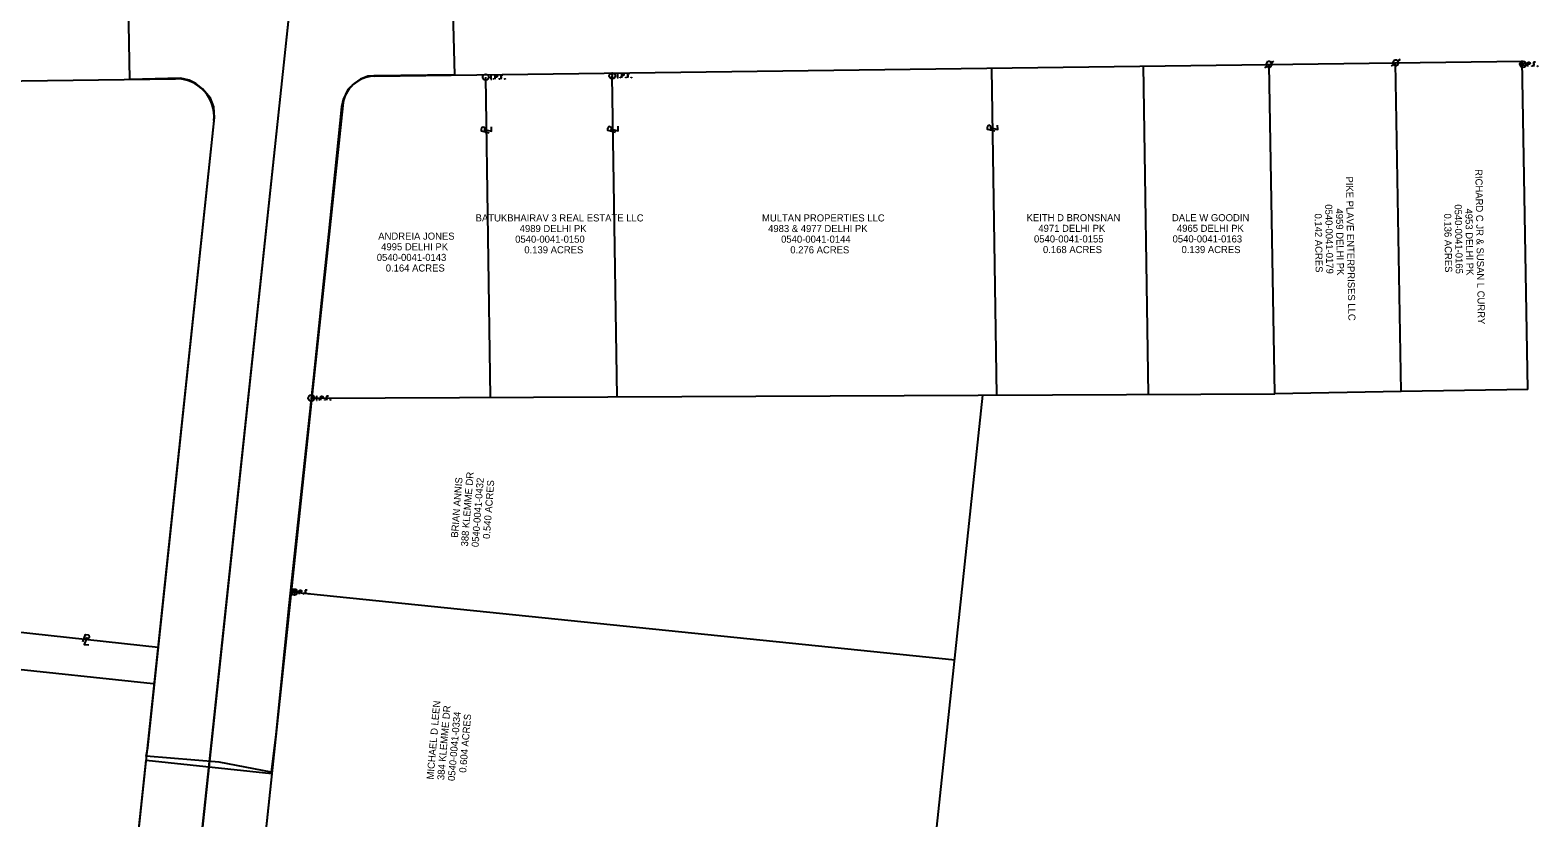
# Model space of a CAD drawing. Extents: x 1369159 to 1370720, y 404461 to 406422.
# Drawn here: x 1369920 to 1370515, y 405578 to 405889 of the extents above; entities that cross this region are included whole.
import ezdxf

# ---------------------------------------------------------------- set-up
doc = ezdxf.new("R2010")
doc.units = 0
for name, color, linetype in [('_CIVIL_CONSTRUCTION', 7, 'Continuous'), ('Default', 7, 'Continuous'), ('DR_P_Cells', 7, 'Continuous'), ('DR_P_Storm_Sewer', 7, 'Continuous'), ('DR_X_Cells', 7, 'Continuous'), ('GK_Drainage_Nodes', 7, 'Continuous'), ('PF_X_Ground_Line', 7, 'Continuous'), ('SC_Scratch1', 7, 'Continuous'), ('UT_X_Water', 7, 'Continuous'), ('XS_X_Pavt', 7, 'Continuous'), ('XS_X_Subgrade', 7, 'Continuous')]:
    doc.layers.add(name, color=color, linetype=linetype)

msp = doc.modelspace()

# ---------------------------------------------------------------- linework, layer by layer
at = {"layer": '_CIVIL_CONSTRUCTION'}
for p, q in [((1370408.45, 405875), (1370407.49, 405874.28)), ((1370408.1, 405875.6), (1370408.81, 405876.8)), ((1370408.81, 405874.39), (1370408.1, 405875.6)), ((1370408.81, 405876.8), (1370409.71, 405876.8)), ((1370409.71, 405874.39), (1370408.81, 405874.39)), ((1370409.71, 405876.8), (1370410.42, 405875.6)), ((1370410.42, 405875.6), (1370409.71, 405874.39)), ((1370411.03, 405876.92), (1370410.07, 405876.2)), ((1370458.44, 405875.63), (1370457.47, 405874.91)), ((1370458.08, 405876.23), (1370458.79, 405877.43)), ((1370458.79, 405875.03), (1370458.08, 405876.23)), ((1370458.79, 405877.43), (1370459.69, 405877.43)), ((1370459.69, 405875.03), (1370458.79, 405875.03)), ((1370459.69, 405877.43), (1370460.4, 405876.23)), ((1370460.4, 405876.23), (1370459.69, 405875.03)), ((1370461.01, 405877.55), (1370460.05, 405876.83))]:
    msp.add_line(p, q, dxfattribs=at)
at = {"layer": 'Default'}
for p, q in [((1370411.48, 405745.39), (1370409.21, 405875.37)), ((1370461.47, 405746.26), (1370459.2, 405876.24)), ((1370511.46, 405747.13), (1370509.2, 405877.11)), ((1370511.46, 405747.13), (1370461.47, 405746.26)), ((1370461.47, 405746.26), (1370411.48, 405745.39))]:
    msp.add_line(p, q, dxfattribs=at)
at = {"layer": 'DR_P_Cells'}
msp.add_line((1370077.92, 406421.94), (1369968.9, 405398.85), dxfattribs=at)
at = {"layer": 'DR_P_Storm_Sewer'}
for p, q in [((1370301.59, 405744.9), (1370299.61, 405873.78)), ((1370361.6, 405745.17), (1370359.6, 405875.04)), ((1370101.6, 405744.01), (1370099.65, 405870.55)), ((1370151.59, 405744.23), (1370149.64, 405871.08)), ((1370099.36, 405848.84), (1370099.34, 405850.14)), ((1370099.97, 405849.66), (1370099.97, 405849.66)), ((1370149.35, 405849.07), (1370149.33, 405850.36)), ((1370149.96, 405849.88), (1370149.96, 405849.88)), ((1370299.36, 405849.54), (1370299.34, 405850.83)), ((1370299.97, 405850.35), (1370299.97, 405850.35)), ((1370030.71, 405743.69), (1370411.48, 405745.39)), ((1370274.45, 405540.93), (1370296.13, 405744.87)), ((1369970.15, 405645.1), (1369714.82, 405673.24)), ((1370024.06, 405667.03), (1370285.18, 405640.18)), ((1369941.02, 405648.94), (1369942.31, 405648.8)), ((1369941.75, 405648.23), (1369941.75, 405648.23))]:
    msp.add_line(p, q, dxfattribs=at)
for points in [[(1370100.96, 405848.45), (1370097.98, 405849.18), (1370097.97, 405850.22)], [(1370099.01, 405849.91), (1370101.98, 405849.16), (1370101.95, 405850.91)], [(1370150.95, 405848.67), (1370147.97, 405849.41), (1370147.96, 405850.44)], [(1370149, 405850.13), (1370151.97, 405849.39), (1370151.94, 405851.13)], [(1370300.96, 405849.14), (1370297.98, 405849.88), (1370297.97, 405850.91)], [(1370299.01, 405850.6), (1370301.98, 405849.85), (1370301.95, 405851.6)], [(1369940.43, 405647.4), (1369941.53, 405650.26), (1369942.56, 405650.15)], [(1369942.12, 405649.15), (1369941.01, 405646.3), (1369942.75, 405646.11)]]:
    msp.add_lwpolyline(points, dxfattribs=at)
for centre, start, end in [((1370098.65, 405850.12), 1.35172, 172.20884), ((1370148.64, 405850.35), 1.35172, 172.20884), ((1370298.65, 405850.82), 1.35172, 172.20884), ((1369942.38, 405649.48), 264.18315, 75.04027)]:
    msp.add_arc(centre, 0.69, start, end, dxfattribs=at)
at = {"layer": 'DR_X_Cells'}
msp.add_lwpolyline([(1370085.17, 405950.93), (1370087.31, 405871.45), (1370055.38, 405871.07), (1370053, 405870.91), (1370050.13, 405869.76), (1370047.85, 405868.19), (1370045.21, 405865.67), (1370043.32, 405861.75), (1370042.61, 405858.87), (1370037.52, 405808.49), (1370035.46, 405788.7), (1370031.53, 405751.98), (1370021.79, 405661.72), (1370016.71, 405610.7), (1370014.88, 405595.8), (1369994.27, 405599.82), (1369965.52, 405602.15), (1369966.06, 405605.47), (1369992.47, 405854.56), (1369992.17, 405858.8), (1369990.88, 405862.22), (1369987.67, 405865.95), (1369985.12, 405868.06), (1369982.45, 405869.36), (1369979.09, 405870.17), (1369959, 405869.67), (1369957.54, 405949.66)], dxfattribs=at)
at = {"layer": 'PF_X_Ground_Line'}
msp.add_line((1369710.16, 405658.01), (1369968.29, 405630.88), dxfattribs=at)
at = {"layer": 'SC_Scratch1'}
for p, q in [((1370151.67, 405871.88), (1370152.02, 405871.88)), ((1370151.84, 405870.28), (1370151.84, 405871.88)), ((1370153.41, 405870.28), (1370153.41, 405871.88)), ((1370153.41, 405871.88), (1370153.94, 405871.88)), ((1370153.94, 405871.88), (1370153.99, 405871.87)), ((1370153.99, 405871.87), (1370154.07, 405871.84)), ((1370154.07, 405871.84), (1370154.1, 405871.82)), ((1370154.1, 405871.82), (1370154.14, 405871.79)), ((1370154.14, 405871.79), (1370154.18, 405871.73)), ((1370154.18, 405871.73), (1370154.21, 405871.67)), ((1370156.42, 405871.88), (1370155.66, 405871.88)), ((1370155.66, 405871.88), (1370155.66, 405870.28)), ((1370511.54, 405874.82), (1370511.54, 405876.42)), ((1370511.54, 405876.42), (1370512.07, 405876.42)), ((1370512.07, 405875.64), (1370511.54, 405875.64)), ((1370512.07, 405876.42), (1370512.13, 405876.41)), ((1370512.16, 405875.65), (1370512.07, 405875.64)), ((1370512.13, 405876.41), (1370512.2, 405876.38)), ((1370512.22, 405875.68), (1370512.16, 405875.65)), ((1370512.2, 405876.38), (1370512.24, 405876.36)), ((1370512.25, 405875.7), (1370512.22, 405875.68)), ((1370512.24, 405876.36), (1370512.27, 405876.33)), ((1370512.29, 405875.74), (1370512.25, 405875.7)), ((1370512.27, 405876.33), (1370512.31, 405876.27)), ((1370512.34, 405875.83), (1370512.29, 405875.74)), ((1370512.31, 405876.27), (1370512.35, 405876.2)), ((1370512.36, 405875.9), (1370512.34, 405875.83)), ((1370512.35, 405876.2), (1370512.37, 405876.1)), ((1370512.37, 405875.95), (1370512.36, 405875.9)), ((1370512.37, 405876.1), (1370512.37, 405875.95)), ((1370513.12, 405874.96), (1370513.15, 405875.01)), ((1370513.12, 405874.89), (1370513.12, 405874.96)), ((1370513.15, 405874.84), (1370513.12, 405874.89)), ((1370513.15, 405875.01), (1370513.19, 405875.03)), ((1370513.19, 405874.82), (1370513.15, 405874.84)), ((1370513.19, 405875.03), (1370513.24, 405875.03)), ((1370513.24, 405874.82), (1370513.19, 405874.82)), ((1370513.24, 405875.03), (1370513.27, 405875.01)), ((1370513.27, 405874.84), (1370513.24, 405874.82)), ((1370513.27, 405875.01), (1370513.31, 405874.96)), ((1370513.31, 405874.89), (1370513.27, 405874.84)), ((1370513.31, 405874.96), (1370513.31, 405874.89)), ((1370514.55, 405876.42), (1370513.79, 405876.42)), ((1370513.79, 405876.42), (1370513.79, 405874.82)), ((1370513.79, 405875.64), (1370514.33, 405875.64)), ((1370515.27, 405874.96), (1370515.3, 405875.01)), ((1370515.27, 405874.89), (1370515.27, 405874.96)), ((1370515.3, 405874.84), (1370515.27, 405874.89)), ((1370515.3, 405875.01), (1370515.34, 405875.03)), ((1370515.34, 405874.82), (1370515.3, 405874.84)), ((1370515.34, 405875.03), (1370515.39, 405875.03)), ((1370515.39, 405874.82), (1370515.34, 405874.82)), ((1370515.39, 405875.03), (1370515.42, 405875.01)), ((1370515.42, 405874.84), (1370515.39, 405874.82)), ((1370515.42, 405875.01), (1370515.46, 405874.96)), ((1370515.46, 405874.89), (1370515.42, 405874.84)), ((1370515.46, 405874.96), (1370515.46, 405874.89)), ((1370101.67, 405871.35), (1370102.02, 405871.35)), ((1370101.67, 405869.76), (1370102.02, 405869.76)), ((1370101.84, 405869.76), (1370101.84, 405871.35)), ((1370102.74, 405869.89), (1370102.77, 405869.94)), ((1370102.74, 405869.83), (1370102.74, 405869.89)), ((1370102.77, 405869.78), (1370102.74, 405869.83)), ((1370102.77, 405869.94), (1370102.8, 405869.97)), ((1370102.8, 405869.76), (1370102.77, 405869.78)), ((1370102.8, 405869.97), (1370102.86, 405869.97)), ((1370102.86, 405869.76), (1370102.8, 405869.76)), ((1370102.86, 405869.97), (1370102.89, 405869.94)), ((1370102.89, 405869.78), (1370102.86, 405869.76)), ((1370102.89, 405869.94), (1370102.92, 405869.89)), ((1370102.92, 405869.83), (1370102.89, 405869.78)), ((1370102.92, 405869.89), (1370102.92, 405869.83)), ((1370103.41, 405869.76), (1370103.41, 405871.35)), ((1370103.41, 405871.35), (1370103.94, 405871.35)), ((1370103.94, 405870.57), (1370103.41, 405870.57)), ((1370103.94, 405871.35), (1370103.99, 405871.34)), ((1370104.03, 405870.59), (1370103.94, 405870.57)), ((1370103.99, 405871.34), (1370104.07, 405871.32)), ((1370104.08, 405870.61), (1370104.03, 405870.59)), ((1370104.07, 405871.32), (1370104.1, 405871.29)), ((1370104.11, 405870.64), (1370104.08, 405870.61)), ((1370104.1, 405871.29), (1370104.14, 405871.27)), ((1370104.16, 405870.67), (1370104.11, 405870.64)), ((1370104.14, 405871.27), (1370104.18, 405871.2)), ((1370104.2, 405870.76), (1370104.16, 405870.67)), ((1370104.18, 405871.2), (1370104.21, 405871.14)), ((1370104.22, 405870.84), (1370104.2, 405870.76)), ((1370104.21, 405871.14), (1370104.24, 405871.04)), ((1370104.24, 405870.89), (1370104.22, 405870.84)), ((1370104.24, 405871.04), (1370104.24, 405870.89)), ((1370104.99, 405869.89), (1370105.02, 405869.94)), ((1370104.99, 405869.83), (1370104.99, 405869.89)), ((1370105.02, 405869.78), (1370104.99, 405869.83)), ((1370105.02, 405869.94), (1370105.05, 405869.97)), ((1370105.05, 405869.76), (1370105.02, 405869.78)), ((1370105.05, 405869.97), (1370105.11, 405869.97)), ((1370105.11, 405869.76), (1370105.05, 405869.76)), ((1370105.11, 405869.97), (1370105.14, 405869.94)), ((1370105.14, 405869.78), (1370105.11, 405869.76)), ((1370105.14, 405869.94), (1370105.17, 405869.89)), ((1370105.17, 405869.83), (1370105.14, 405869.78)), ((1370105.17, 405869.89), (1370105.17, 405869.83)), ((1370106.42, 405871.35), (1370105.66, 405871.35)), ((1370105.66, 405871.35), (1370105.66, 405869.76)), ((1370105.66, 405870.57), (1370106.2, 405870.57)), ((1370107.13, 405869.89), (1370107.17, 405869.94)), ((1370107.13, 405869.83), (1370107.13, 405869.89)), ((1370107.17, 405869.78), (1370107.13, 405869.83)), ((1370107.17, 405869.94), (1370107.2, 405869.97)), ((1370107.2, 405869.76), (1370107.17, 405869.78)), ((1370107.2, 405869.97), (1370107.26, 405869.97)), ((1370107.26, 405869.76), (1370107.2, 405869.76)), ((1370107.26, 405869.97), (1370107.29, 405869.94)), ((1370107.29, 405869.78), (1370107.26, 405869.76)), ((1370107.29, 405869.94), (1370107.32, 405869.89)), ((1370107.32, 405869.83), (1370107.29, 405869.78)), ((1370107.32, 405869.89), (1370107.32, 405869.83)), ((1370149.64, 405871.2), (1370149.64, 405870.31)), ((1370151.67, 405870.28), (1370152.02, 405870.28)), ((1370152.74, 405870.42), (1370152.77, 405870.47)), ((1370152.74, 405870.36), (1370152.74, 405870.42)), ((1370152.77, 405870.31), (1370152.74, 405870.36)), ((1370152.77, 405870.47), (1370152.8, 405870.49)), ((1370152.8, 405870.28), (1370152.77, 405870.31)), ((1370152.8, 405870.49), (1370152.86, 405870.49)), ((1370152.86, 405870.28), (1370152.8, 405870.28)), ((1370152.86, 405870.49), (1370152.89, 405870.47)), ((1370152.89, 405870.31), (1370152.86, 405870.28)), ((1370152.89, 405870.47), (1370152.92, 405870.42)), ((1370152.92, 405870.36), (1370152.89, 405870.31)), ((1370152.92, 405870.42), (1370152.92, 405870.36)), ((1370153.94, 405871.1), (1370153.41, 405871.1)), ((1370154.03, 405871.11), (1370153.94, 405871.1)), ((1370154.08, 405871.14), (1370154.03, 405871.11)), ((1370154.12, 405871.16), (1370154.08, 405871.14)), ((1370154.16, 405871.2), (1370154.12, 405871.16)), ((1370154.2, 405871.29), (1370154.16, 405871.2)), ((1370154.23, 405871.36), (1370154.2, 405871.29)), ((1370154.21, 405871.67), (1370154.24, 405871.56)), ((1370154.24, 405871.41), (1370154.23, 405871.36)), ((1370154.24, 405871.56), (1370154.24, 405871.41)), ((1370154.99, 405870.42), (1370155.02, 405870.47)), ((1370154.99, 405870.36), (1370154.99, 405870.42)), ((1370155.02, 405870.31), (1370154.99, 405870.36)), ((1370155.02, 405870.47), (1370155.05, 405870.49)), ((1370155.05, 405870.28), (1370155.02, 405870.31)), ((1370155.05, 405870.49), (1370155.11, 405870.49)), ((1370155.11, 405870.28), (1370155.05, 405870.28)), ((1370155.11, 405870.49), (1370155.14, 405870.47)), ((1370155.14, 405870.31), (1370155.11, 405870.28)), ((1370155.14, 405870.47), (1370155.17, 405870.42)), ((1370155.17, 405870.36), (1370155.14, 405870.31)), ((1370155.17, 405870.42), (1370155.17, 405870.36)), ((1370155.66, 405871.1), (1370156.2, 405871.1)), ((1370157.14, 405870.42), (1370157.17, 405870.47)), ((1370157.14, 405870.36), (1370157.14, 405870.42)), ((1370157.17, 405870.31), (1370157.14, 405870.36)), ((1370157.17, 405870.47), (1370157.2, 405870.49)), ((1370157.2, 405870.28), (1370157.17, 405870.31)), ((1370157.2, 405870.49), (1370157.26, 405870.49)), ((1370157.26, 405870.28), (1370157.2, 405870.28)), ((1370157.26, 405870.49), (1370157.29, 405870.47)), ((1370157.29, 405870.31), (1370157.26, 405870.28)), ((1370157.29, 405870.47), (1370157.32, 405870.42)), ((1370157.32, 405870.36), (1370157.29, 405870.31)), ((1370157.32, 405870.42), (1370157.32, 405870.36)), ((1370032.72, 405744.49), (1370033.07, 405744.49)), ((1370032.72, 405742.89), (1370033.07, 405742.89)), ((1370032.9, 405742.89), (1370032.9, 405744.49)), ((1370033.79, 405743.03), (1370033.82, 405743.08)), ((1370033.79, 405742.97), (1370033.79, 405743.03)), ((1370033.82, 405742.92), (1370033.79, 405742.97)), ((1370033.82, 405743.08), (1370033.86, 405743.11)), ((1370033.86, 405742.89), (1370033.82, 405742.92)), ((1370033.86, 405743.11), (1370033.91, 405743.11)), ((1370033.91, 405742.89), (1370033.86, 405742.89)), ((1370033.91, 405743.11), (1370033.95, 405743.08)), ((1370033.95, 405742.92), (1370033.91, 405742.89)), ((1370033.95, 405743.08), (1370033.98, 405743.03)), ((1370033.98, 405742.97), (1370033.95, 405742.92)), ((1370033.98, 405743.03), (1370033.98, 405742.97)), ((1370034.46, 405742.89), (1370034.46, 405744.49)), ((1370034.46, 405744.49), (1370034.99, 405744.49)), ((1370034.99, 405743.71), (1370034.46, 405743.71)), ((1370034.99, 405744.49), (1370035.05, 405744.48)), ((1370035.08, 405743.73), (1370034.99, 405743.71)), ((1370035.05, 405744.48), (1370035.12, 405744.46)), ((1370035.14, 405743.75), (1370035.08, 405743.73)), ((1370035.12, 405744.46), (1370035.16, 405744.43)), ((1370035.17, 405743.78), (1370035.14, 405743.75)), ((1370035.16, 405744.43), (1370035.19, 405744.41)), ((1370035.21, 405743.81), (1370035.17, 405743.78)), ((1370035.19, 405744.41), (1370035.23, 405744.34)), ((1370035.26, 405743.9), (1370035.21, 405743.81)), ((1370035.23, 405744.34), (1370035.27, 405744.28)), ((1370035.28, 405743.98), (1370035.26, 405743.9)), ((1370035.27, 405744.28), (1370035.29, 405744.18)), ((1370035.29, 405744.03), (1370035.28, 405743.98)), ((1370035.29, 405744.18), (1370035.29, 405744.03)), ((1370036.04, 405743.03), (1370036.07, 405743.08)), ((1370036.04, 405742.97), (1370036.04, 405743.03)), ((1370036.07, 405742.92), (1370036.04, 405742.97)), ((1370036.07, 405743.08), (1370036.11, 405743.11)), ((1370036.11, 405742.89), (1370036.07, 405742.92)), ((1370036.11, 405743.11), (1370036.16, 405743.11)), ((1370036.16, 405742.89), (1370036.11, 405742.89)), ((1370036.16, 405743.11), (1370036.19, 405743.08)), ((1370036.19, 405742.92), (1370036.16, 405742.89)), ((1370036.19, 405743.08), (1370036.23, 405743.03)), ((1370036.23, 405742.97), (1370036.19, 405742.92)), ((1370036.23, 405743.03), (1370036.23, 405742.97)), ((1370037.47, 405744.49), (1370036.71, 405744.49)), ((1370036.71, 405744.49), (1370036.71, 405742.89)), ((1370036.71, 405743.71), (1370037.25, 405743.71)), ((1370038.19, 405743.03), (1370038.22, 405743.08)), ((1370038.19, 405742.97), (1370038.19, 405743.03)), ((1370038.22, 405742.92), (1370038.19, 405742.97)), ((1370038.22, 405743.08), (1370038.25, 405743.11)), ((1370038.25, 405742.89), (1370038.22, 405742.92)), ((1370038.25, 405743.11), (1370038.31, 405743.11)), ((1370038.31, 405742.89), (1370038.25, 405742.89)), ((1370038.31, 405743.11), (1370038.34, 405743.08)), ((1370038.34, 405742.92), (1370038.31, 405742.89)), ((1370038.34, 405743.08), (1370038.38, 405743.03)), ((1370038.38, 405742.97), (1370038.34, 405742.92)), ((1370038.38, 405743.03), (1370038.38, 405742.97)), ((1370026.05, 405666.23), (1370026.05, 405667.83)), ((1370026.05, 405667.83), (1370026.58, 405667.83)), ((1370026.58, 405667.05), (1370026.05, 405667.05)), ((1370026.58, 405667.83), (1370026.64, 405667.82)), ((1370026.67, 405667.06), (1370026.58, 405667.05)), ((1370026.64, 405667.82), (1370026.71, 405667.79)), ((1370026.73, 405667.09), (1370026.67, 405667.06)), ((1370026.71, 405667.79), (1370026.75, 405667.77)), ((1370026.76, 405667.11), (1370026.73, 405667.09)), ((1370026.75, 405667.77), (1370026.78, 405667.74)), ((1370026.8, 405667.15), (1370026.76, 405667.11)), ((1370026.78, 405667.74), (1370026.82, 405667.68)), ((1370026.85, 405667.24), (1370026.8, 405667.15)), ((1370026.82, 405667.68), (1370026.86, 405667.62)), ((1370026.87, 405667.31), (1370026.85, 405667.24)), ((1370026.86, 405667.62), (1370026.88, 405667.51)), ((1370026.88, 405667.36), (1370026.87, 405667.31)), ((1370026.88, 405667.51), (1370026.88, 405667.36)), ((1370027.63, 405666.37), (1370027.66, 405666.42)), ((1370027.63, 405666.31), (1370027.63, 405666.37)), ((1370027.66, 405666.26), (1370027.63, 405666.31)), ((1370027.66, 405666.42), (1370027.7, 405666.44)), ((1370027.7, 405666.23), (1370027.66, 405666.26)), ((1370027.7, 405666.44), (1370027.75, 405666.44)), ((1370027.75, 405666.23), (1370027.7, 405666.23)), ((1370027.75, 405666.44), (1370027.78, 405666.42)), ((1370027.78, 405666.26), (1370027.75, 405666.23)), ((1370027.78, 405666.42), (1370027.82, 405666.37)), ((1370027.82, 405666.31), (1370027.78, 405666.26)), ((1370027.82, 405666.37), (1370027.82, 405666.31)), ((1370029.06, 405667.83), (1370028.3, 405667.83)), ((1370028.3, 405667.83), (1370028.3, 405666.23)), ((1370028.3, 405667.05), (1370028.84, 405667.05)), ((1370029.78, 405666.37), (1370029.81, 405666.42)), ((1370029.78, 405666.31), (1370029.78, 405666.37)), ((1370029.81, 405666.26), (1370029.78, 405666.31)), ((1370029.81, 405666.42), (1370029.85, 405666.44)), ((1370029.85, 405666.23), (1370029.81, 405666.26)), ((1370029.85, 405666.44), (1370029.9, 405666.44)), ((1370029.9, 405666.23), (1370029.85, 405666.23)), ((1370029.9, 405666.44), (1370029.93, 405666.42)), ((1370029.93, 405666.26), (1370029.9, 405666.23)), ((1370029.93, 405666.42), (1370029.97, 405666.37)), ((1370029.97, 405666.31), (1370029.93, 405666.26)), ((1370029.97, 405666.37), (1370029.97, 405666.31))]:
    msp.add_line(p, q, dxfattribs=at)
for centre, radius in [((1370099.65, 405870.55), 1.2), ((1370149.64, 405871.08), 1.2), ((1370149.64, 405871.73), 0.16), ((1370509.55, 405875.62), 1.2), ((1370509.55, 405875.62), 0.495), ((1370030.71, 405743.69), 1.2), ((1370024.06, 405667.03), 1.2), ((1370024.06, 405667.03), 0.495)]:
    msp.add_circle(centre, radius, dxfattribs=at)
at = {"layer": 'UT_X_Water'}
msp.add_lwpolyline([(1369941.6, 405376.85), (1369965.4, 405600.58), (1370015.12, 405595.3), (1369991.32, 405371.56), (1369966.44, 405374.21)], dxfattribs=at)
at = {"layer": 'XS_X_Pavt'}
msp.add_line((1370023.41, 405910.39), (1369966.45, 405374.29), dxfattribs=at)
at = {"layer": 'XS_X_Subgrade'}
for p, q in [((1370055.88, 405870.97), (1370509.2, 405876.92)), ((1369789.17, 405867.23), (1369977.07, 405869.94)), ((1370043.12, 405859.34), (1369991.31, 405371.65)), ((1369992.21, 405853.35), (1369941.59, 405376.93))]:
    msp.add_line(p, q, dxfattribs=at)
for centre, radius, start, end in [((1369977.29, 405854.94), 15, 353.93523, 90.82604), ((1370056.05, 405857.97), 13, 90.75218, 173.93523)]:
    msp.add_arc(centre, radius, start, end, dxfattribs=at)

# ---------------------------------------------------------------- texts
at = {"layer": 'GK_Drainage_Nodes'}
for s, rotation, p in [('PIKE PLAVE ENTERPRISES LLC', 271, (1370439.6, 405831.26)), ('RICHARD C JR & SUSAN L CURRY', 271, (1370490.71, 405834.17)), ('0540-0041-0179', 271, (1370431.39, 405820.27)), ('4959 DELHI PK', 271, (1370435.62, 405818.6)), ('0540-0041-0165', 271, (1370482.55, 405820.25)), ('4953 DELHI PK', 271, (1370486.78, 405818.6)), ('0.142 ACRES', 271, (1370427.25, 405816.63)), ('0.136 ACRES', 271, (1370478.41, 405816.63)), ('BRIAN ANNIS', 85.61455, (1370088.67, 405688.42)), ('388 KLEMME DR', 85.61455, (1370092.62, 405684.97)), ('0540-0041-0432', 85.61455, (1370096.81, 405684.71)), ('0.540 ACRES', 85.61455, (1370101.27, 405687.94)), ('MICHAEL D LEEN', 85.05214, (1370079.03, 405592.86)), ('384 KLEMME DR', 85.05214, (1370083.23, 405592.63)), ('0540-0041-0334', 85.05214, (1370087.41, 405592.26)), ('0.604 ACRES', 85.05214, (1370091.91, 405595.51))]:
    msp.add_text(s, height=2.8, rotation=rotation, dxfattribs=at).set_placement(p)
for s, p in [('BATUKBHAIRAV 3 REAL ESTATE LLC', (1370095.67, 405813.51)), ('4989 DELHI PK', (1370113.08, 405809.31)), ('MULTAN PROPERTIES LLC', (1370208.84, 405813.51)), ('4983 & 4977 DELHI PK', (1370211.25, 405809.31)), ('KEITH D BRONSNAN ', (1370313.41, 405813.6)), ('4971 DELHI PK', (1370318.06, 405809.4)), ('DALE W GOODIN', (1370370.85, 405813.6)), ('4965 DELHI PK', (1370372.82, 405809.4)), ('ANDREIA JONES', (1370057.18, 405806.31)), ('0540-0041-0150', (1370111.29, 405805.11)), ('0540-0041-0144', (1370216.39, 405805.11)), ('0540-0041-0155', (1370316.33, 405805.2)), ('0540-0041-0163', (1370371.1, 405805.2)), ('0540-0041-0143', (1370056.6, 405797.91)), ('4995 DELHI PK', (1370058.33, 405802.11)), ('0.139 ACRES', (1370114.91, 405800.91)), ('0.276 ACRES', (1370220.02, 405800.91)), ('0.168 ACRES', (1370319.89, 405801)), ('0.139 ACRES', (1370374.64, 405801)), ('0.164 ACRES', (1370060.15, 405793.71))]:
    msp.add_text(s, height=2.8, dxfattribs=at).set_placement(p)

doc.saveas('drawing.dxf')
